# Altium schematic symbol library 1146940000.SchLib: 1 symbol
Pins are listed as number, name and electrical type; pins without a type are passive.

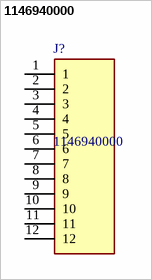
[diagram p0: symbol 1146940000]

## 1146940000
designator J?
PCB plug-in connector, male header, open side, THT solder connection, 5.08 mm, Number of poles: 12, 90, Solder pin length: 3.2 mm, tinned, orange, Box; Manufacturer_Name: Weidmuller; Geometry.Height: 8.4mm
footprint 1146940000
pins: 1, 2, 3, 4, 5, 6, 7, 8, 9, 10, 11, 12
